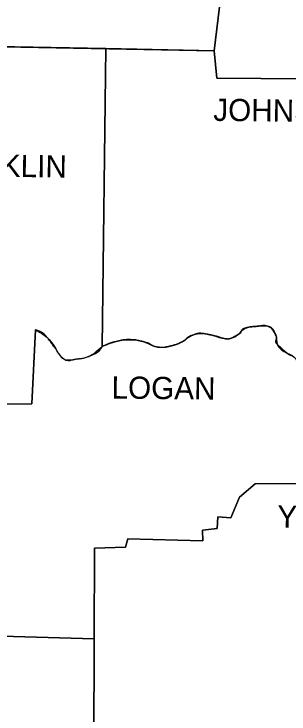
# Model space of a CAD drawing. Extents: x -28335 to 1228743, y -22428 to 152440.
# Drawn here: x 26423 to 27629, y 11936 to 15008 of the extents above; entities that cross this region are included whole.
import ezdxf

# ---------------------------------------------------------------- set-up
doc = ezdxf.new("R2010")
doc.units = 0
doc.layers.add('16', color=7, linetype='Continuous')
doc.layers.add('8', color=7, linetype='Continuous')

msp = doc.modelspace()

# ---------------------------------------------------------------- linework, layer by layer
at = {"layer": '16'}
for p, q in [((26810, 13549.1), (26825.8, 14856.1)), ((26825.8, 14856.1), (26810, 13549.1)), ((26825.8, 14856.2), (26825.8, 14856.1)), ((26825.8, 14856.1), (27301.5, 14847.1)), ((27301.5, 14847.1), (26825.8, 14856.1)), ((27301.5, 14847.1), (27312.9, 14727)), ((27312.9, 14727), (27301.5, 14847.1)), ((27312.9, 14727), (28932.4, 14713.9)), ((28369.2, 14718.5), (27312.9, 14727)), ((27249.6, 13606), (27251.7, 13605.7)), ((27577.9, 13558.2), (27615.6, 13523.8)), ((27041.9, 13548.9), (27050.1, 13546.9)), ((27317.4, 12801.6), (27315.1, 12749.5)), ((27315.1, 12749.5), (27249.4, 12742.7)), ((26923.2, 12704.2), (26911.9, 12667.9)), ((26776, 12663.4), (26774.6, 12266.1)), ((26911.9, 12667.9), (26776, 12663.4)), ((26774.6, 12266.1), (26771.5, 11338.2))]:
    msp.add_line(p, q, dxfattribs=at)
for points in [[(26327.5, 16480.3), (26144, 15954.8), (26107.7, 15114.4), (26080.5, 15112.1), (26067.3, 14865.5), (26066.9, 14858.4), (26200.6, 14847.1), (26221, 14867.5), (26825.8, 14856.1)], [(27430.3, 16079.9), (27439.7, 15952.5), (27543.9, 15945.7), (27516.7, 15565.2), (27469.2, 15567.5), (27460.1, 15506.3), (27405.7, 15506.3), (27403.5, 15402.1), (27369.5, 15399.8), (27358.2, 15266.2), (27308.3, 15259.4), (27301.5, 15055.5), (27324.2, 15039.6), (27301.5, 14847.1)], [(27301.5, 14847.1), (27324.2, 15039.6), (27301.5, 15055.5), (27308.3, 15259.4)], [(26825.8, 14856.1), (26825.8, 14856.1), (26266.3, 14866.6)], [(26825.8, 14856.1), (26825.8, 14856.2)], [(25897.4, 12943.2), (25899.3, 13007.7), (26191.5, 13000.9), (26207.4, 13295.4), (26501.9, 13297.7), (26517.7, 13621.6)], [(26517.7, 13621.6), (26501.9, 13297.7), (26207.4, 13295.4)], [(26774.6, 12266.1), (26776, 12663.4), (26911.9, 12667.9), (26923.2, 12704.2), (27251.7, 12695.1), (27249.4, 12742.7), (27315.1, 12749.5), (27317.4, 12801.6), (27374, 12797.1), (27412.5, 12887.7), (27480.5, 12946.6), (27997, 12948.8), (28006, 13275)], [(28006, 13275), (27997, 12948.8), (27480.5, 12946.6), (27412.5, 12887.7)], [(25897.4, 12943.2), (25890.3, 12704.2), (25584.4, 12701.9), (25575.4, 12398.4), (25767.9, 12387), (25761.1, 12294.2), (26774.6, 12266.1)], [(27412.5, 12887.7), (27374, 12797.1), (27317.4, 12801.6)], [(27249.4, 12742.7), (27251.7, 12695.1), (26923.2, 12704.2)], [(26774.6, 12266.1), (25761.1, 12294.2), (25767.9, 12387), (25575.4, 12398.4), (25580.9, 12584.5)], [(26137.2, 11055.1), (26291.2, 11041.5), (26293.5, 11179.7), (26452.1, 11184.2), (26449.8, 11220.4), (26556.3, 11220.4), (26558.5, 11270.3), (26667.3, 11268), (26658.2, 11336), (26771.5, 11338.2), (26774.6, 12266.1)]]:
    msp.add_lwpolyline(points, dxfattribs=at)
for points, degree in [([(28006, 13275), (27992.2, 13289.2), (27977.5, 13302.3), (27963, 13315.8), (27948.5, 13329.3), (27936.6, 13347.1), (27917.7, 13354.3), (27901.5, 13360.5), (27884.5, 13362.1), (27867.9, 13365.6), (27842.2, 13371.1), (27816.5, 13376.5), (27790.8, 13381.5), (27774.5, 13384.7), (27757.5, 13374.4), (27741, 13377), (27730.3, 13378.6), (27720.4, 13383.2), (27711.6, 13390.6), (27703.2, 13397.5), (27697.2, 13404.8), (27691.2, 13413.2), (27683.3, 13424.1), (27676.8, 13435.5), (27670.8, 13447.2), (27663.3, 13461.6), (27670.7, 13482.3), (27659.5, 13494.8), (27648.9, 13506.5), (27633, 13510.3), (27620.9, 13519.7), (27605.7, 13531.5), (27590.5, 13543.2), (27577.9, 13558.2), (27568.9, 13568.9), (27577.7, 13586.3), (27571.1, 13599), (27562.9, 13614.6), (27554.1, 13632.2), (27537.1, 13637.5), (27521.4, 13642.3), (27505.3, 13639), (27489.6, 13637.5), (27471.3, 13635.7), (27453.1, 13634.2), (27435.2, 13628.4), (27421.2, 13623.9), (27417.3, 13606), (27403.5, 13599), (27385.4, 13589.8), (27367.3, 13579.8), (27349.1, 13583.1), (27332.5, 13586.1), (27316.1, 13592.9), (27299.3, 13596.7), (27283.5, 13600.2), (27267.6, 13603.7), (27251.7, 13605.7), (27235.1, 13607.8), (27218.4, 13603.6), (27201.9, 13596.7), (27184.2, 13589.3), (27173.1, 13574.8), (27156.6, 13567.2), (27141.9, 13560.5), (27126.9, 13555.3), (27111.3, 13551.4), (27091.3, 13546.3), (27069.8, 13543.3), (27050.1, 13546.9), (27030.5, 13550.4), (27013.4, 13564.7), (26993.5, 13569.5), (26975.5, 13573.9), (26957.3, 13577.7), (26939.1, 13578.6), (26921.1, 13579.4), (26902.7, 13578.1), (26884.7, 13574), (26858.7, 13568.1), (26834.1, 13560.4), (26810, 13549.1)], 3), ([(27419.3, 13614.7), (27423.8, 13620.6), (27428.2, 13626.1), (27435.2, 13628.4), (27453.1, 13634.2), (27471.3, 13635.7), (27489.6, 13637.5), (27505.3, 13639), (27521.4, 13642.3), (27537.1, 13637.5)], 3), ([(26567.6, 13589.9), (26555.2, 13605.6), (26536.1, 13615.8), (26517.7, 13621.6)], 2), ([(27341.6, 13584.7), (27344.1, 13584.1), (27346.6, 13583.6), (27349.1, 13583.1), (27367.3, 13579.8), (27385.4, 13589.8), (27403.5, 13599), (27410.4, 13602.5), (27414.8, 13608.8), (27419.3, 13614.7)], 3), ([(27537.1, 13637.5), (27554.1, 13632.2), (27562.9, 13614.6), (27571.1, 13599)], 2), ([(27156.6, 13567.2), (27173.1, 13574.8), (27184.2, 13589.3), (27201.9, 13596.7)], 2), ([(27201.9, 13596.7), (27217.7, 13603.3), (27233.7, 13607.5), (27249.6, 13606)], 2), ([(27251.7, 13605.7), (27267.6, 13603.7), (27283.5, 13600.2), (27299.3, 13596.7), (27313.6, 13593.5), (27327.5, 13588.1), (27341.6, 13584.7)], 3), ([(27571.1, 13599), (27577.7, 13586.3), (27568.9, 13568.9), (27577.9, 13558.2)], 2), ([(26810, 13549.1), (26797.8, 13524), (26768.9, 13511.3), (26742, 13501.5), (26727, 13496.1), (26711.9, 13494.3), (26696.7, 13492.5), (26678.1, 13490.3), (26655.9, 13481), (26640.1, 13494.8)], 3), ([(26810, 13549.1), (26834.1, 13560.4), (26858.7, 13568.1), (26884.7, 13574), (26902.7, 13578.1), (26921.1, 13579.4), (26939.1, 13578.6), (26957.3, 13577.7), (26975.5, 13573.9), (26993.5, 13569.5), (27000.4, 13567.8), (27007, 13565), (27013.5, 13561.8)], 3), ([(27013.5, 13561.8), (27023, 13557.2), (27032.2, 13552.1), (27041.9, 13548.9)], 2), ([(27060, 13545.6), (27076.9, 13544.4), (27094.6, 13547.2), (27111.3, 13551.4)], 2), ([(27111.3, 13551.4), (27126.9, 13555.3), (27141.9, 13560.5), (27156.6, 13567.2)], 2), ([(27050.1, 13546.9), (27053.4, 13546.3), (27056.7, 13545.9), (27060, 13545.6)], 2), ([(27615.6, 13523.8), (27617.4, 13522.5), (27619.2, 13521.1), (27620.9, 13519.7)], 2), ([(27620.9, 13519.7), (27625.5, 13516.1), (27630.7, 13513.3), (27635.9, 13510.7)], 2)]:
    msp.add_open_spline(points, degree=degree, dxfattribs=at)
for points in [[(26517.7, 13621.6), (26567.6, 13589.9), (26606.1, 13537.8), (26640.1, 13494.8), (26696.7, 13492.5), (26742, 13501.5), (26810, 13549.1)], [(26606.1, 13537.8), (26596.5, 13550.8), (26587, 13563.9), (26577.5, 13576.9), (26567.6, 13589.9)], [(26640.1, 13494.8), (26629.9, 13505), (26621.5, 13515.8), (26613.9, 13526.8), (26606.1, 13537.8)]]:
    msp.add_spline(points, degree=3, dxfattribs=at)
at = {"layer": '8'}
for points in [[(24439, 16052.3), (24870.9, 16049.9), (24882.2, 16199.5), (25038.5, 16199.5), (25052.1, 16441.8), (25935.6, 16410.1), (25962.7, 16478.1), (26327.5, 16480.3), (26144, 15954.8), (26107.7, 15114.4), (26080.5, 15112.1), (26066.9, 14858.4), (26200.6, 14847.1), (26221, 14867.5), (27301.5, 14847.1), (27312.9, 14727)], [(27430.3, 16079.9), (27439.7, 15952.5), (27543.9, 15945.7), (27516.7, 15565.2), (27469.2, 15567.5), (27460.1, 15506.3), (27405.7, 15506.3), (27403.5, 15402.1), (27369.5, 15399.8), (27358.2, 15266.2), (27308.3, 15259.4), (27301.5, 15055.5), (27324.2, 15039.6), (27301.5, 14847.1)], [(27312.9, 14727), (29827.4, 14706.7), (29838.7, 14944.5), (30429, 14937.6)], [(26825.8, 14856.2), (26810, 13549.1)], [(26517.7, 13621.6), (26501.9, 13297.7), (26207.4, 13295.4), (26191.5, 13000.9), (25899.3, 13007.7), (25890.3, 12704.2), (25584.4, 12701.9), (25575.4, 12398.4), (25767.9, 12387), (25761.1, 12294.2), (26774.6, 12266.1)], [(28006, 13275), (27997, 12948.8), (27480.5, 12946.6), (27412.5, 12887.7), (27374, 12797.1), (27317.4, 12801.6), (27315.1, 12749.5), (27249.4, 12742.7), (27251.7, 12695.1), (26923.2, 12704.2), (26911.9, 12667.9), (26776, 12663.4), (26774.6, 12266.1)], [(26774.6, 12266.1), (26771.5, 11338.2), (26658.2, 11336), (26667.3, 11268), (26558.5, 11270.3), (26556.3, 11220.4), (26449.8, 11220.4), (26452.1, 11184.2), (26293.5, 11179.7), (26291.2, 11041.5), (26137.2, 11055.1), (26112.3, 9940.6), (25240.1, 9942.8), (25219.7, 9684.6), (25251.4, 9662), (25249.2, 9372), (24596, 9400.7)]]:
    msp.add_lwpolyline(points, dxfattribs=at)
for points in [[(26810, 13549.1), (26884.7, 13574), (26939.1, 13578.6), (26993.5, 13569.5), (27050.1, 13546.9), (27111.3, 13551.4), (27156.6, 13567.2), (27201.9, 13596.7), (27251.7, 13605.7), (27299.3, 13596.7), (27349.1, 13583.1), (27403.5, 13599), (27435.2, 13628.4), (27489.6, 13637.5), (27537.1, 13637.5), (27571.1, 13599), (27577.9, 13558.2), (27620.9, 13519.7), (27659.5, 13494.8), (27670.8, 13447.2), (27691.2, 13413.2), (27711.6, 13390.6), (27741, 13377), (27790.8, 13381.5), (27867.9, 13365.6), (27917.7, 13354.3), (27963, 13315.8), (28006, 13275)], [(26517.7, 13621.6), (26567.6, 13589.9), (26606.1, 13537.8), (26640.1, 13494.8), (26696.7, 13492.5), (26742, 13501.5), (26810, 13549.1)]]:
    msp.add_spline(points, degree=3, dxfattribs=at)

# ---------------------------------------------------------------- texts
for s, rotation, p in [('JOHNSON', 359.3514, (27297, 14539)), ('FRANKLIN', 359.1816, (26010.3, 14298.9)), ('LOGAN', 359.3969, (26850.7, 13320.3)), ('YELL', 359.1987, (27577.9, 12754))]:
    msp.add_text(s, height=97.42, rotation=rotation, dxfattribs=at).set_placement(p)

doc.saveas('drawing.dxf')
